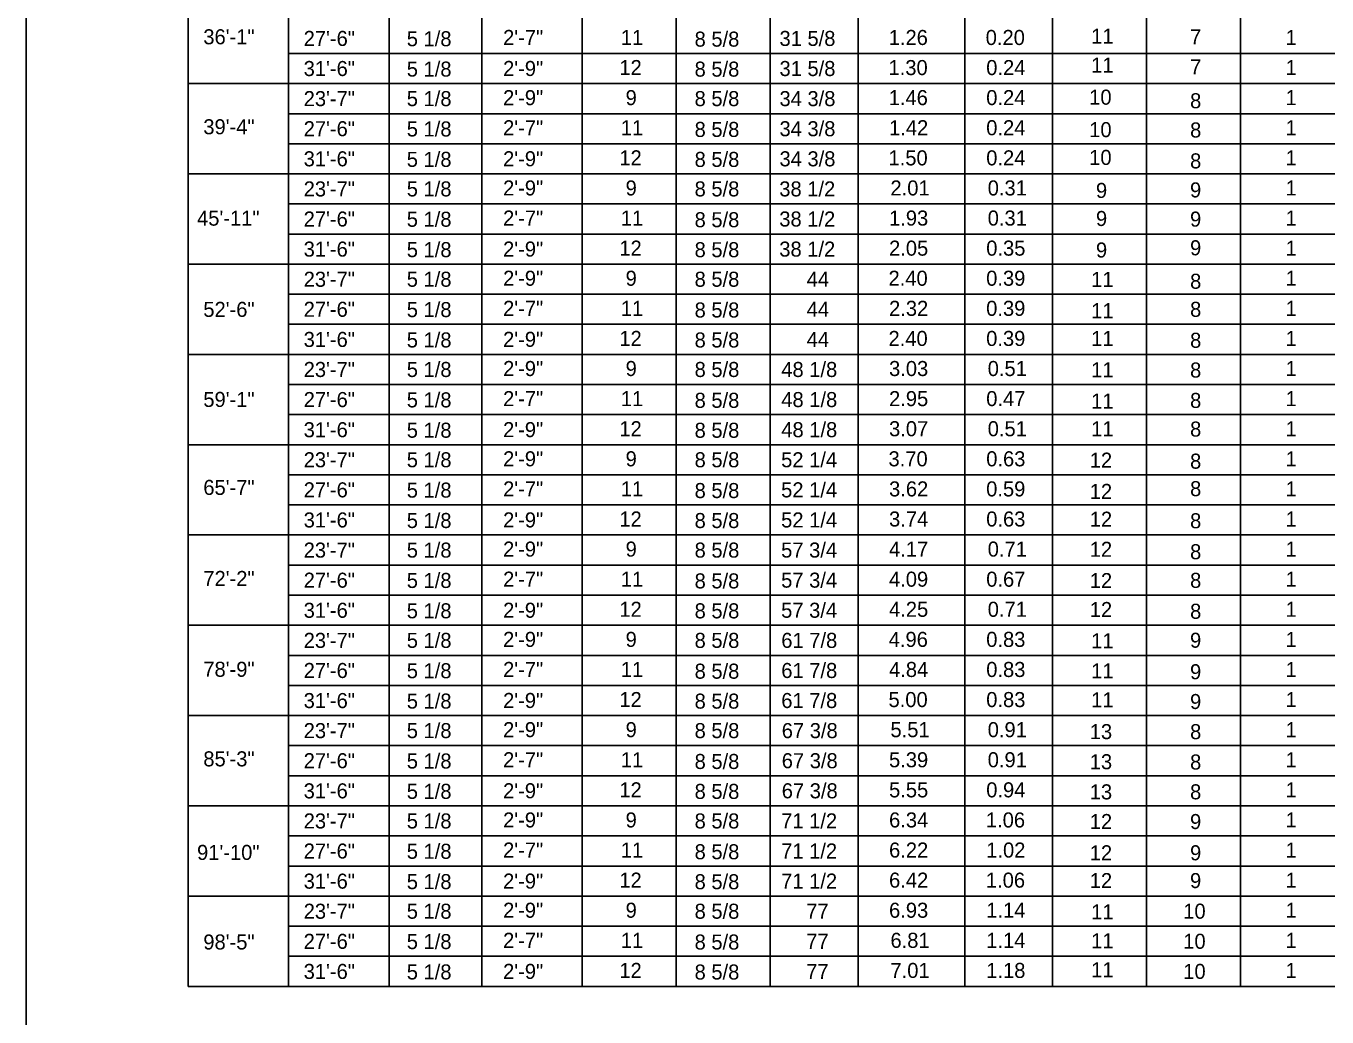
# Model space of a CAD drawing. Extents: x -5022 to -159, y 1126 to 7226.
# Drawn here: x -3800.1 to -3540.8, y 6085.4 to 6283 of the extents above; entities that cross this region are included whole.
import ezdxf

# ---------------------------------------------------------------- set-up
doc = ezdxf.new("R2010")
doc.units = 0
doc.layers.add('2', color=7, linetype='Continuous')
doc.layers.add('3', color=7, linetype='Continuous')

msp = doc.modelspace()

# ---------------------------------------------------------------- linework, layer by layer
at = {"layer": '2'}
msp.add_line((-3800.13, 5892.81), (-3800.13, 6456.81), dxfattribs=at)
at = {"layer": '3'}
for p, q in [((-3767.78, 6442.31), (-3767.78, 6091.5)), ((-3747.78, 6424.31), (-3747.78, 6091.5)), ((-3727.78, 6424.31), (-3727.78, 6091.5)), ((-3709.28, 6424.31), (-3709.28, 6091.5)), ((-3689.28, 6424.31), (-3689.28, 6091.5)), ((-3670.53, 6424.31), (-3670.53, 6091.5)), ((-3651.78, 6424.31), (-3651.78, 6091.5)), ((-3634.28, 6423.93), (-3634.28, 6091.5)), ((-3613.03, 6424.31), (-3613.03, 6091.5)), ((-3595.53, 6424.31), (-3595.53, 6091.5)), ((-3576.78, 6424.31), (-3576.78, 6091.5)), ((-3558.03, 6424.31), (-3558.03, 6091.5)), ((-3747.78, 6277.5), (-3053.03, 6277.5)), ((-3767.78, 6271.5), (-3053.03, 6271.5)), ((-3747.78, 6265.5), (-3053.03, 6265.5)), ((-3747.78, 6259.5), (-3053.03, 6259.5)), ((-3767.78, 6253.5), (-3053.03, 6253.5)), ((-3747.78, 6247.5), (-3053.03, 6247.5)), ((-3747.78, 6241.5), (-3053.03, 6241.5)), ((-3767.78, 6235.5), (-3053.03, 6235.5)), ((-3747.78, 6229.5), (-3053.03, 6229.5)), ((-3747.78, 6223.5), (-3053.03, 6223.5)), ((-3767.78, 6217.5), (-3053.03, 6217.5)), ((-3747.78, 6211.5), (-3053.03, 6211.5)), ((-3747.78, 6205.5), (-3053.03, 6205.5)), ((-3767.78, 6199.5), (-3053.03, 6199.5)), ((-3747.78, 6193.5), (-3053.03, 6193.5)), ((-3747.78, 6187.5), (-3053.03, 6187.5)), ((-3767.78, 6181.5), (-3053.03, 6181.5)), ((-3747.78, 6175.5), (-3053.03, 6175.5)), ((-3747.78, 6169.5), (-3053.03, 6169.5)), ((-3767.78, 6163.5), (-3053.03, 6163.5)), ((-3747.78, 6157.5), (-3053.03, 6157.5)), ((-3747.78, 6151.5), (-3053.03, 6151.5)), ((-3767.78, 6145.5), (-3053.03, 6145.5)), ((-3747.78, 6139.5), (-3053.03, 6139.5)), ((-3747.78, 6133.5), (-3053.03, 6133.5)), ((-3767.78, 6127.49), (-3053.03, 6127.5)), ((-3747.78, 6121.49), (-3053.03, 6121.5)), ((-3747.78, 6115.49), (-3053.03, 6115.5)), ((-3767.78, 6109.49), (-3053.03, 6109.5)), ((-3747.78, 6103.5), (-3053.03, 6103.5)), ((-3747.78, 6097.5), (-3053.03, 6097.5)), ((-3767.78, 6091.5), (-3053.03, 6091.5))]:
    msp.add_line(p, q, dxfattribs=at)

# ---------------------------------------------------------------- texts
at = {"layer": '2'}
for s, p in [('36\'-1"', (-3764.79, 6279.33)), ('27\'-6"', (-3744.79, 6279)), ('5 1/8', (-3724.24, 6278.94)), ('2\'-7"', (-3705.04, 6279.19)), ('11', (-3681.58, 6279.19)), ('8 5/8', (-3666.87, 6278.86)), ('31 5/8', (-3649.95, 6279)), ('1.26', (-3628.18, 6279.19)), ('0.20', (-3608.85, 6279.19)), ('11', (-3587.83, 6279.45)), ('7', (-3568.11, 6279.32)), ('1', (-3549.07, 6279.19)), ('31\'-6"', (-3744.79, 6273)), ('5 1/8', (-3724.24, 6272.89)), ('2\'-9"', (-3705.04, 6273.01)), ('12', (-3681.87, 6273.19)), ('8 5/8', (-3666.87, 6272.88)), ('31 5/8', (-3649.95, 6273)), ('1.30', (-3628.22, 6273.19)), ('0.24', (-3608.74, 6273.19)), ('11', (-3587.83, 6273.68)), ('7', (-3568.11, 6273.31)), ('1', (-3549.07, 6273.19)), ('23\'-7"', (-3744.79, 6267)), ('5 1/8', (-3724.24, 6267)), ('2\'-9"', (-3705.04, 6267.19)), ('9', (-3680.62, 6267.2)), ('8 5/8', (-3666.87, 6267)), ('34 3/8', (-3649.95, 6267)), ('1.46', (-3628.18, 6267.2)), ('0.24', (-3608.74, 6267.2)), ('10', (-3588.22, 6267.29)), ('1', (-3549.07, 6267.2)), ('8', (-3568.11, 6266.58)), ('39\'-4"', (-3764.79, 6261.39)), ('27\'-6"', (-3744.79, 6261)), ('5 1/8', (-3724.24, 6260.95)), ('2\'-7"', (-3705.04, 6261.19)), ('11', (-3681.58, 6261.2)), ('8 5/8', (-3666.87, 6260.86)), ('34 3/8', (-3649.95, 6261)), ('1.42', (-3628.11, 6261.2)), ('0.24', (-3608.74, 6261.2)), ('10', (-3588.22, 6260.82)), ('8', (-3568.11, 6260.75)), ('1', (-3549.07, 6261.2)), ('31\'-6"', (-3744.79, 6255)), ('5 1/8', (-3724.24, 6254.89)), ('2\'-9"', (-3705.04, 6255.01)), ('12', (-3681.87, 6255.19)), ('8 5/8', (-3666.87, 6254.88)), ('34 3/8', (-3649.95, 6255)), ('1.50', (-3628.22, 6255.19)), ('0.24', (-3608.74, 6255.19)), ('10', (-3588.22, 6255.28)), ('8', (-3568.11, 6254.59)), ('1', (-3549.07, 6255.19)), ('23\'-7"', (-3744.79, 6249)), ('5 1/8', (-3724.24, 6249)), ('2\'-9"', (-3705.04, 6249.19)), ('9', (-3680.62, 6249.19)), ('8 5/8', (-3666.87, 6249)), ('38 1/2', (-3649.99, 6249)), ('2.01', (-3627.83, 6249.19)), ('0.31', (-3608.45, 6249.19)), ('1', (-3549.07, 6249.19)), ('9', (-3586.87, 6248.7)), ('9', (-3568.12, 6248.8)), ('45\'-11"', (-3766.04, 6243.17)), ('27\'-6"', (-3744.79, 6243)), ('5 1/8', (-3724.24, 6242.95)), ('2\'-7"', (-3705.04, 6243.19)), ('11', (-3681.58, 6243.19)), ('8 5/8', (-3666.87, 6242.86)), ('38 1/2', (-3649.99, 6243)), ('1.93', (-3628.11, 6243.19)), ('0.31', (-3608.45, 6243.19)), ('9', (-3586.87, 6243.1)), ('9', (-3568.12, 6242.98)), ('1', (-3549.07, 6243.19)), ('31\'-6"', (-3744.79, 6237)), ('5 1/8', (-3724.24, 6236.89)), ('2\'-9"', (-3705.04, 6237.01)), ('12', (-3681.87, 6237.19)), ('8 5/8', (-3666.87, 6236.88)), ('38 1/2', (-3649.99, 6237)), ('2.05', (-3628.11, 6237.19)), ('0.35', (-3608.74, 6237.19)), ('9', (-3586.87, 6236.82)), ('9', (-3568.12, 6237.26)), ('1', (-3549.07, 6237.19)), ('23\'-7"', (-3744.79, 6230.99)), ('5 1/8', (-3724.24, 6230.99)), ('2\'-9"', (-3705.04, 6231.19)), ('9', (-3680.62, 6231.19)), ('8 5/8', (-3666.87, 6230.99)), ('44', (-3644.53, 6231)), ('2.40', (-3628.22, 6231.19)), ('0.39', (-3608.75, 6231.19)), ('11', (-3587.83, 6230.96)), ('1', (-3549.07, 6231.19)), ('8', (-3568.11, 6230.59)), ('52\'-6"', (-3764.79, 6224.98)), ('27\'-6"', (-3744.79, 6225)), ('5 1/8', (-3724.24, 6224.94)), ('2\'-7"', (-3705.04, 6225.19)), ('11', (-3681.58, 6225.19)), ('8 5/8', (-3666.87, 6224.86)), ('44', (-3644.53, 6225)), ('2.32', (-3628.11, 6225.19)), ('0.39', (-3608.75, 6225.19)), ('11', (-3587.83, 6224.72)), ('8', (-3568.11, 6224.99)), ('1', (-3549.07, 6225.19)), ('31\'-6"', (-3744.79, 6218.99)), ('5 1/8', (-3724.24, 6218.89)), ('2\'-9"', (-3705.04, 6219.01)), ('12', (-3681.87, 6219.19)), ('8 5/8', (-3666.87, 6218.88)), ('44', (-3644.53, 6219)), ('2.40', (-3628.22, 6219.19)), ('0.39', (-3608.75, 6219.19)), ('11', (-3587.83, 6219.18)), ('8', (-3568.11, 6218.82)), ('1', (-3549.07, 6219.19)), ('23\'-7"', (-3744.79, 6213)), ('5 1/8', (-3724.24, 6213)), ('2\'-9"', (-3705.04, 6213.19)), ('9', (-3680.62, 6213.19)), ('8 5/8', (-3666.87, 6213)), ('48 1/8', (-3649.59, 6213)), ('3.03', (-3628.11, 6213.19)), ('0.51', (-3608.45, 6213.19)), ('11', (-3587.83, 6212.94)), ('8', (-3568.11, 6212.89)), ('1', (-3549.07, 6213.19)), ('59\'-1"', (-3764.79, 6207.03)), ('27\'-6"', (-3744.79, 6207)), ('5 1/8', (-3724.24, 6206.94)), ('2\'-7"', (-3705.04, 6207.19)), ('11', (-3681.58, 6207.19)), ('8 5/8', (-3666.87, 6206.85)), ('48 1/8', (-3649.59, 6207)), ('2.95', (-3628.11, 6207.19)), ('0.47', (-3608.74, 6207.19)), ('11', (-3587.83, 6206.71)), ('8', (-3568.11, 6206.83)), ('1', (-3549.07, 6207.19)), ('31\'-6"', (-3744.79, 6200.99)), ('5 1/8', (-3724.24, 6200.89)), ('2\'-9"', (-3705.04, 6201.01)), ('12', (-3681.87, 6201.19)), ('8 5/8', (-3666.87, 6200.88)), ('48 1/8', (-3649.59, 6201)), ('3.07', (-3628.11, 6201.19)), ('0.51', (-3608.45, 6201.19)), ('11', (-3587.83, 6201.17)), ('8', (-3568.11, 6201.12)), ('1', (-3549.07, 6201.19)), ('23\'-7"', (-3744.79, 6195)), ('5 1/8', (-3724.24, 6195)), ('2\'-9"', (-3705.04, 6195.19)), ('9', (-3680.62, 6195.19)), ('8 5/8', (-3666.87, 6195)), ('52 1/4', (-3649.62, 6195)), ('3.70', (-3628.22, 6195.19)), ('0.63', (-3608.74, 6195.19)), ('12', (-3588.11, 6194.92)), ('8', (-3568.11, 6194.72)), ('1', (-3549.07, 6195.19)), ('65\'-7"', (-3764.79, 6189.49)), ('3.62', (-3628.11, 6189.19)), ('0.59', (-3608.75, 6189.19)), ('8', (-3568.11, 6189.24)), ('27\'-6"', (-3744.79, 6189)), ('5 1/8', (-3724.24, 6188.95)), ('2\'-7"', (-3705.04, 6189.19)), ('11', (-3681.58, 6189.19)), ('8 5/8', (-3666.87, 6188.86)), ('52 1/4', (-3649.62, 6189)), ('12', (-3588.11, 6188.69)), ('1', (-3549.07, 6189.19)), ('31\'-6"', (-3744.79, 6183)), ('5 1/8', (-3724.24, 6182.89)), ('2\'-9"', (-3705.04, 6183.01)), ('12', (-3681.87, 6183.19)), ('8 5/8', (-3666.87, 6182.88)), ('52 1/4', (-3649.62, 6183)), ('3.74', (-3628.11, 6183.19)), ('0.63', (-3608.74, 6183.19)), ('12', (-3588.11, 6183.15)), ('8', (-3568.11, 6182.84)), ('1', (-3549.07, 6183.19)), ('23\'-7"', (-3744.79, 6176.99)), ('5 1/8', (-3724.24, 6176.99)), ('2\'-9"', (-3705.04, 6177.19)), ('9', (-3680.62, 6177.19)), ('8 5/8', (-3666.87, 6176.99)), ('57 3/4', (-3649.62, 6177)), ('4.17', (-3628.11, 6177.19)), ('0.71', (-3608.45, 6177.19)), ('12', (-3588.11, 6177.15)), ('8', (-3568.11, 6176.67)), ('1', (-3549.07, 6177.19)), ('72\'-2"', (-3764.79, 6171.33)), ('5 1/8', (-3724.24, 6170.94)), ('2\'-7"', (-3705.04, 6171.19)), ('11', (-3681.58, 6171.19)), ('57 3/4', (-3649.62, 6171)), ('4.09', (-3628.12, 6171.19)), ('0.67', (-3608.74, 6171.19)), ('1', (-3549.07, 6171.19)), ('27\'-6"', (-3744.79, 6170.99)), ('8 5/8', (-3666.87, 6170.85)), ('12', (-3588.11, 6170.91)), ('8', (-3568.11, 6170.96)), ('31\'-6"', (-3744.79, 6164.99)), ('5 1/8', (-3724.24, 6164.89)), ('2\'-9"', (-3705.04, 6165)), ('12', (-3681.87, 6165.19)), ('8 5/8', (-3666.87, 6164.88)), ('57 3/4', (-3649.62, 6165)), ('4.25', (-3628.11, 6165.19)), ('0.71', (-3608.45, 6165.19)), ('12', (-3588.11, 6165.14)), ('8', (-3568.11, 6164.79)), ('1', (-3549.07, 6165.19)), ('23\'-7"', (-3744.79, 6158.99)), ('5 1/8', (-3724.24, 6158.99)), ('2\'-9"', (-3705.04, 6159.19)), ('9', (-3680.62, 6159.19)), ('8 5/8', (-3666.87, 6158.99)), ('61 7/8', (-3649.59, 6158.99)), ('4.96', (-3628.18, 6159.19)), ('0.83', (-3608.74, 6159.19)), ('11', (-3587.83, 6158.91)), ('9', (-3568.12, 6159.02)), ('1', (-3549.07, 6159.19)), ('78\'-9"', (-3764.79, 6153.23)), ('27\'-6"', (-3744.79, 6152.99)), ('5 1/8', (-3724.24, 6152.94)), ('2\'-7"', (-3705.04, 6153.19)), ('11', (-3681.58, 6153.19)), ('8 5/8', (-3666.87, 6152.85)), ('61 7/8', (-3649.59, 6152.99)), ('4.84', (-3628.11, 6153.19)), ('0.83', (-3608.74, 6153.19)), ('1', (-3549.07, 6153.19)), ('11', (-3587.83, 6152.9)), ('9', (-3568.12, 6152.74)), ('31\'-6"', (-3744.79, 6146.99)), ('5 1/8', (-3724.24, 6146.89)), ('2\'-9"', (-3705.04, 6147.01)), ('12', (-3681.87, 6147.19)), ('8 5/8', (-3666.87, 6146.88)), ('61 7/8', (-3649.59, 6147)), ('5.00', (-3628.22, 6147.19)), ('0.83', (-3608.74, 6147.19)), ('11', (-3587.83, 6147.13)), ('9', (-3568.12, 6146.8)), ('1', (-3549.07, 6147.19)), ('23\'-7"', (-3744.79, 6141)), ('5 1/8', (-3724.24, 6141)), ('2\'-9"', (-3705.04, 6141.19)), ('9', (-3680.62, 6141.19)), ('8 5/8', (-3666.87, 6141)), ('67 3/8', (-3649.5, 6141)), ('5.51', (-3627.83, 6141.19)), ('0.91', (-3608.45, 6141.19)), ('13', (-3588.11, 6140.8)), ('8', (-3568.11, 6140.79)), ('1', (-3549.07, 6141.19)), ('85\'-3"', (-3764.79, 6135.37)), ('27\'-6"', (-3744.79, 6135)), ('5 1/8', (-3724.24, 6134.94)), ('2\'-7"', (-3705.04, 6135.19)), ('11', (-3681.58, 6135.19)), ('8 5/8', (-3666.87, 6134.85)), ('67 3/8', (-3649.5, 6135)), ('5.39', (-3628.12, 6135.19)), ('0.91', (-3608.45, 6135.19)), ('13', (-3588.11, 6134.8)), ('1', (-3549.07, 6135.19)), ('8', (-3568.11, 6134.74)), ('31\'-6"', (-3744.79, 6128.99)), ('5 1/8', (-3724.24, 6128.89)), ('2\'-9"', (-3705.04, 6129.01)), ('12', (-3681.87, 6129.19)), ('8 5/8', (-3666.87, 6128.88)), ('67 3/8', (-3649.5, 6129)), ('5.55', (-3628.11, 6129.19)), ('0.94', (-3608.74, 6129.19)), ('13', (-3588.11, 6128.79)), ('8', (-3568.11, 6128.8)), ('1', (-3549.07, 6129.19)), ('23\'-7"', (-3744.79, 6122.99)), ('5 1/8', (-3724.24, 6122.99)), ('2\'-9"', (-3705.04, 6123.19)), ('9', (-3680.62, 6123.19)), ('8 5/8', (-3666.87, 6122.99)), ('71 1/2', (-3649.62, 6123)), ('6.34', (-3628.11, 6123.19)), ('1.06', (-3608.81, 6123.19)), ('12', (-3588.11, 6122.87)), ('9', (-3568.12, 6122.87)), ('1', (-3549.07, 6123.19)), ('91\'-10"', (-3766.04, 6116.72)), ('27\'-6"', (-3744.79, 6116.99)), ('5 1/8', (-3724.24, 6116.94)), ('2\'-7"', (-3705.04, 6117.19)), ('11', (-3681.58, 6117.19)), ('8 5/8', (-3666.87, 6116.85)), ('71 1/2', (-3649.62, 6117)), ('6.22', (-3628.11, 6117.19)), ('1.02', (-3608.74, 6117.19)), ('12', (-3588.11, 6116.64)), ('9', (-3568.12, 6116.64)), ('1', (-3549.07, 6117.19)), ('31\'-6"', (-3744.79, 6110.99)), ('5 1/8', (-3724.24, 6110.89)), ('2\'-9"', (-3705.04, 6111)), ('12', (-3681.87, 6111.19)), ('8 5/8', (-3666.87, 6110.87)), ('71 1/2', (-3649.62, 6111)), ('6.42', (-3628.11, 6111.19)), ('1.06', (-3608.81, 6111.19)), ('12', (-3588.11, 6111.1)), ('9', (-3568.12, 6111.1)), ('1', (-3549.07, 6111.19)), ('23\'-7"', (-3744.79, 6104.99)), ('5 1/8', (-3724.24, 6104.99)), ('2\'-9"', (-3705.04, 6105.19)), ('9', (-3680.62, 6105.19)), ('8 5/8', (-3666.87, 6104.99)), ('77', (-3644.62, 6105)), ('6.93', (-3628.11, 6105.19)), ('1.14', (-3608.74, 6105.19)), ('11', (-3587.83, 6104.87)), ('10', (-3569.47, 6105)), ('1', (-3549.07, 6105.19)), ('98\'-5"', (-3764.79, 6098.86)), ('27\'-6"', (-3744.79, 6098.99)), ('5 1/8', (-3724.24, 6098.94)), ('2\'-7"', (-3705.04, 6099.19)), ('11', (-3681.58, 6099.19)), ('8 5/8', (-3666.87, 6098.85)), ('77', (-3644.62, 6098.99)), ('6.81', (-3627.83, 6099.19)), ('1.14', (-3608.74, 6099.19)), ('11', (-3587.83, 6099.1)), ('10', (-3569.47, 6099)), ('1', (-3549.07, 6099.19)), ('11', (-3587.83, 6093.32)), ('31\'-6"', (-3744.79, 6092.99)), ('5 1/8', (-3724.24, 6092.89)), ('2\'-9"', (-3705.04, 6093)), ('12', (-3681.87, 6093.19)), ('8 5/8', (-3666.87, 6092.87)), ('77', (-3644.62, 6092.99)), ('7.01', (-3627.83, 6093.19)), ('1.18', (-3608.74, 6093.19)), ('10', (-3569.47, 6093)), ('1', (-3549.07, 6093.19))]:
    msp.add_text(s, height=3, dxfattribs=at).set_placement(p)

doc.saveas('drawing.dxf')
